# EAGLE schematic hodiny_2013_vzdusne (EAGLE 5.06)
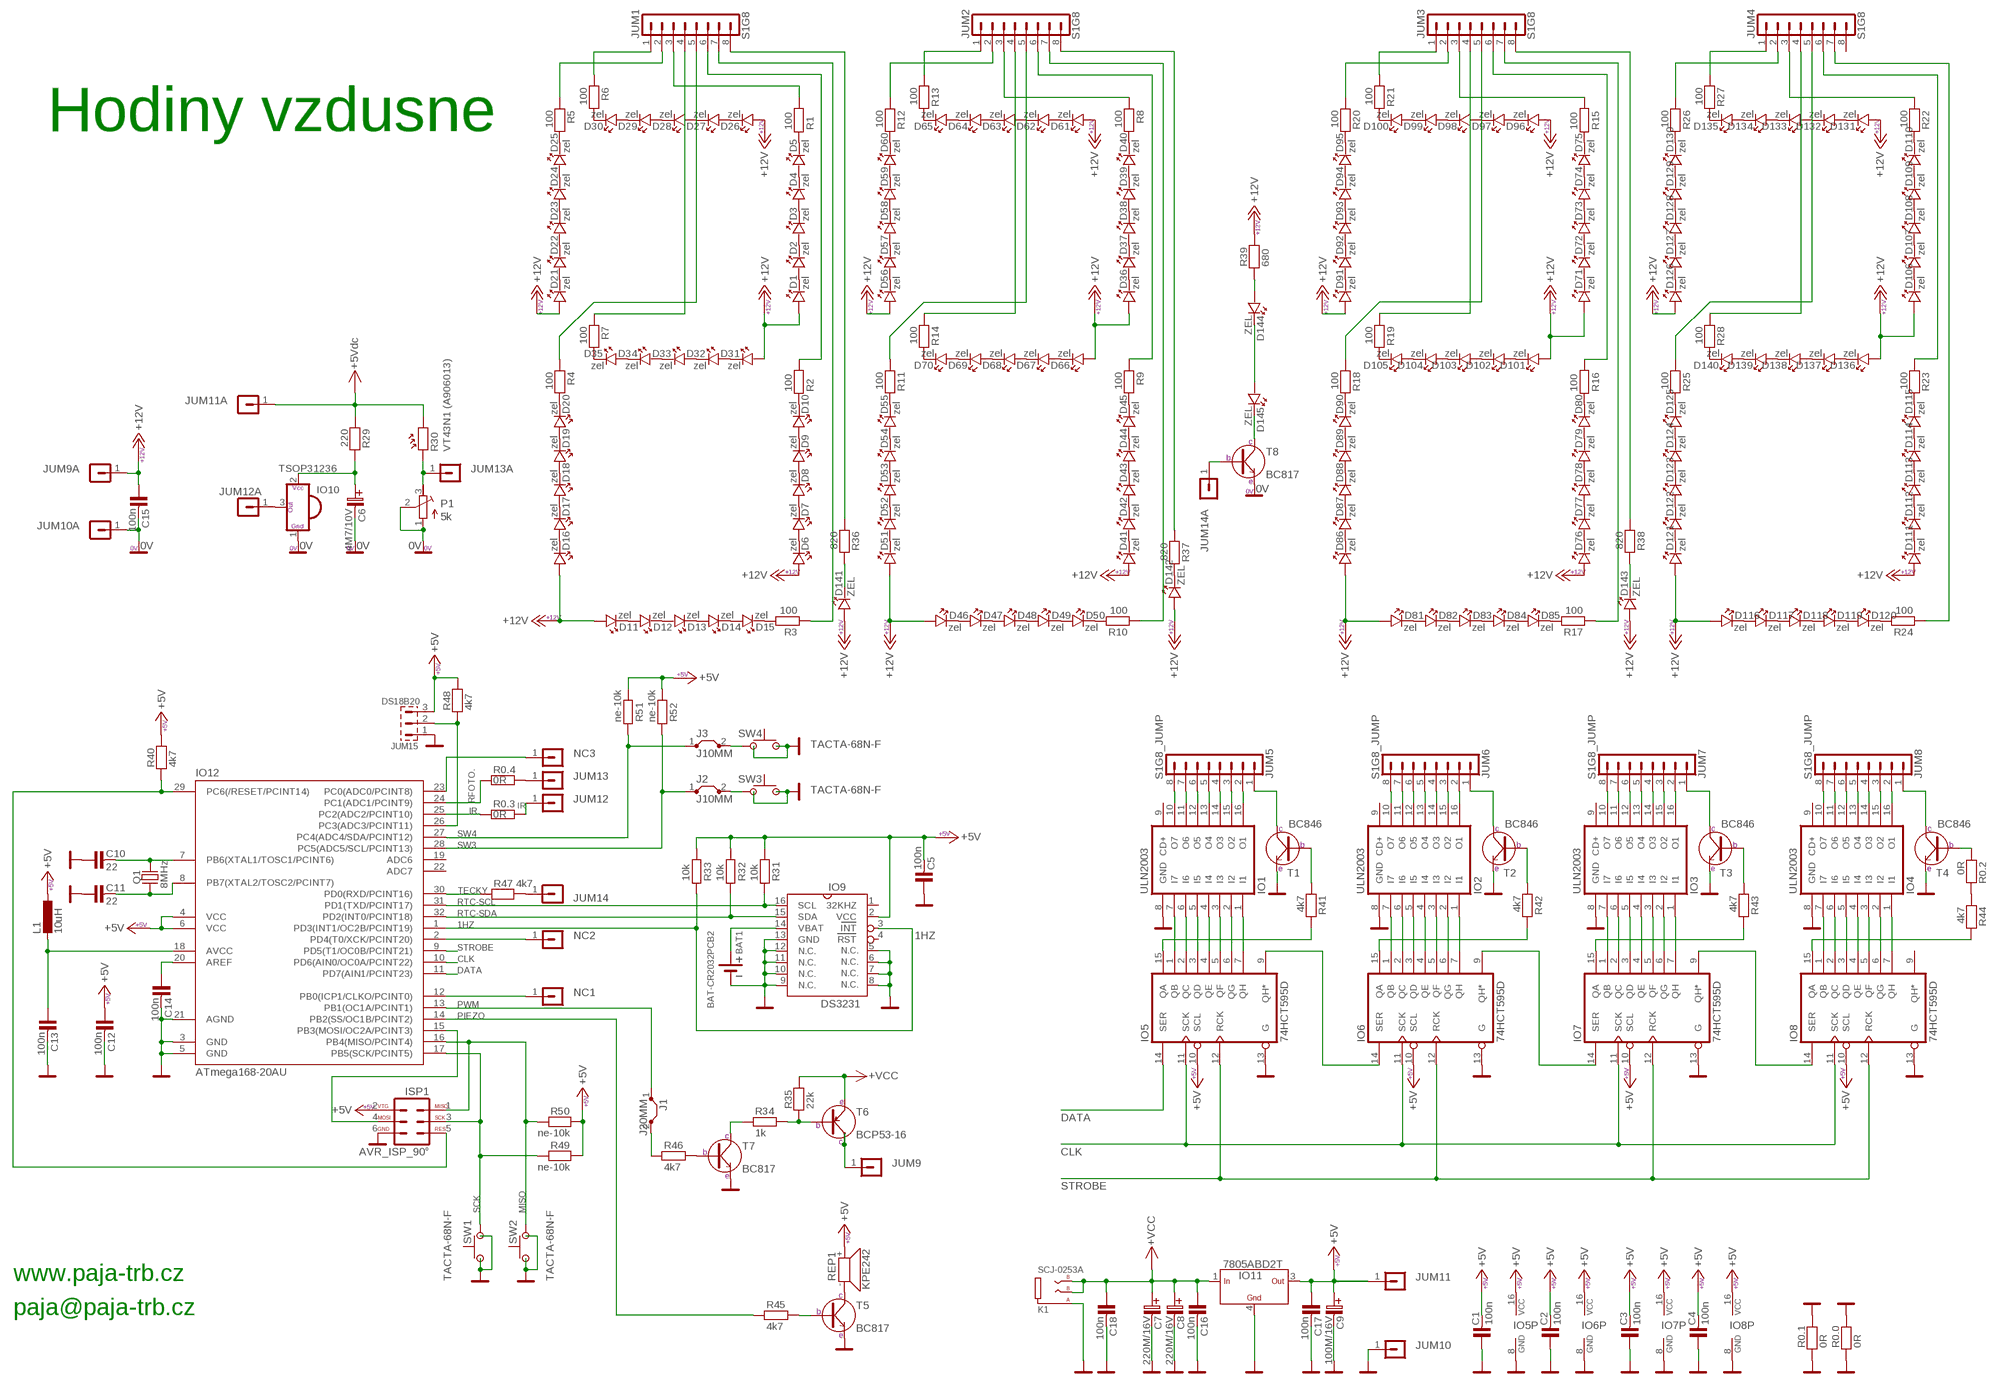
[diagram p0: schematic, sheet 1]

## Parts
BAT1  BAT-CR2032PCB2  2032  [SN2032]
C1  100n  C-KERAMIK_SMD_1206  [1206]
C2  100n  C-KERAMIK_SMD_1206  [1206]
C3  100n  C-KERAMIK_SMD_1206  [1206]
C4  100n  C-KERAMIK_SMD_1206  [1206]
C5  100n  C-KERAMIK_SMD_1206  [1206]
C6  4M7/10V  [A]
C7  220M/16V  #_SMD_POUZDRAF  [C_EL-SMD_F]
C8  220M/16V  #_SMD_POUZDRAF  [C_EL-SMD_F]
C9  100M/16V  100M/16V_SMD  [C_EL-SMD_D]
C10  22  C-KERAMIK_SMD_0805  [0805]
C11  22  C-KERAMIK_SMD_0805  [0805]
C12  100n  C-KERAMIK_SMD_0805  [0805]
C13  100n  C-KERAMIK_SMD_0805  [0805]
C14  100n  C-KERAMIK_SMD_0805  [0805]
C15  100n  C-KERAMIK_SMD_1206  [1206]
C16  100n  C-KERAMIK_SMD_1206  [1206]
C17  100n  C-KERAMIK_SMD_1206  [1206]
C18  100n  C-KERAMIK_SMD_1206  [1206]
D1  zel  LED_5X5  [LED_5X5]
D2  zel  LED_5X5  [LED_5X5]
D3  zel  LED_5X5  [LED_5X5]
D4  zel  LED_5X5  [LED_5X5]
D5  zel  LED_5X5  [LED_5X5]
D6  zel  LED_5X5  [LED_5X5]
D7  zel  LED_5X5  [LED_5X5]
D8  zel  LED_5X5  [LED_5X5]
D9  zel  LED_5X5  [LED_5X5]
D10  zel  LED_5X5  [LED_5X5]
D11  zel  LED_5X5  [LED_5X5]
D12  zel  LED_5X5  [LED_5X5]
D13  zel  LED_5X5  [LED_5X5]
D14  zel  LED_5X5  [LED_5X5]
D15  zel  LED_5X5  [LED_5X5]
D16  zel  LED_5X5  [LED_5X5]
D17  zel  LED_5X5  [LED_5X5]
D18  zel  LED_5X5  [LED_5X5]
D19  zel  LED_5X5  [LED_5X5]
D20  zel  LED_5X5  [LED_5X5]
D21  zel  LED_5X5  [LED_5X5]
D22  zel  LED_5X5  [LED_5X5]
D23  zel  LED_5X5  [LED_5X5]
D24  zel  LED_5X5  [LED_5X5]
D25  zel  LED_5X5  [LED_5X5]
D26  zel  LED_5X5  [LED_5X5]
D27  zel  LED_5X5  [LED_5X5]
D28  zel  LED_5X5  [LED_5X5]
D29  zel  LED_5X5  [LED_5X5]
D30  zel  LED_5X5  [LED_5X5]
D31  zel  LED_5X5  [LED_5X5]
D32  zel  LED_5X5  [LED_5X5]
D33  zel  LED_5X5  [LED_5X5]
D34  zel  LED_5X5  [LED_5X5]
D35  zel  LED_5X5  [LED_5X5]
D36  zel  LED_5X5  [LED_5X5]
D37  zel  LED_5X5  [LED_5X5]
D38  zel  LED_5X5  [LED_5X5]
D39  zel  LED_5X5  [LED_5X5]
D40  zel  LED_5X5  [LED_5X5]
D41  zel  LED_5X5  [LED_5X5]
D42  zel  LED_5X5  [LED_5X5]
D43  zel  LED_5X5  [LED_5X5]
D44  zel  LED_5X5  [LED_5X5]
D45  zel  LED_5X5  [LED_5X5]
D46  zel  LED_5X5  [LED_5X5]
D47  zel  LED_5X5  [LED_5X5]
D48  zel  LED_5X5  [LED_5X5]
D49  zel  LED_5X5  [LED_5X5]
D50  zel  LED_5X5  [LED_5X5]
D51  zel  LED_5X5  [LED_5X5]
D52  zel  LED_5X5  [LED_5X5]
D53  zel  LED_5X5  [LED_5X5]
D54  zel  LED_5X5  [LED_5X5]
D55  zel  LED_5X5  [LED_5X5]
D56  zel  LED_5X5  [LED_5X5]
D57  zel  LED_5X5  [LED_5X5]
D58  zel  LED_5X5  [LED_5X5]
D59  zel  LED_5X5  [LED_5X5]
D60  zel  LED_5X5  [LED_5X5]
D61  zel  LED_5X5  [LED_5X5]
D62  zel  LED_5X5  [LED_5X5]
D63  zel  LED_5X5  [LED_5X5]
D64  zel  LED_5X5  [LED_5X5]
D65  zel  LED_5X5  [LED_5X5]
D66  zel  LED_5X5  [LED_5X5]
D67  zel  LED_5X5  [LED_5X5]
D68  zel  LED_5X5  [LED_5X5]
D69  zel  LED_5X5  [LED_5X5]
D70  zel  LED_5X5  [LED_5X5]
D71  zel  LED_5X5  [LED_5X5]
D72  zel  LED_5X5  [LED_5X5]
D73  zel  LED_5X5  [LED_5X5]
D74  zel  LED_5X5  [LED_5X5]
D75  zel  LED_5X5  [LED_5X5]
D76  zel  LED_5X5  [LED_5X5]
D77  zel  LED_5X5  [LED_5X5]
D78  zel  LED_5X5  [LED_5X5]
D79  zel  LED_5X5  [LED_5X5]
D80  zel  LED_5X5  [LED_5X5]
D81  zel  LED_5X5  [LED_5X5]
D82  zel  LED_5X5  [LED_5X5]
D83  zel  LED_5X5  [LED_5X5]
D84  zel  LED_5X5  [LED_5X5]
D85  zel  LED_5X5  [LED_5X5]
D86  zel  LED_5X5  [LED_5X5]
D87  zel  LED_5X5  [LED_5X5]
D88  zel  LED_5X5  [LED_5X5]
D89  zel  LED_5X5  [LED_5X5]
D90  zel  LED_5X5  [LED_5X5]
D91  zel  LED_5X5  [LED_5X5]
D92  zel  LED_5X5  [LED_5X5]
D93  zel  LED_5X5  [LED_5X5]
D94  zel  LED_5X5  [LED_5X5]
D95  zel  LED_5X5  [LED_5X5]
D96  zel  LED_5X5  [LED_5X5]
D97  zel  LED_5X5  [LED_5X5]
D98  zel  LED_5X5  [LED_5X5]
D99  zel  LED_5X5  [LED_5X5]
D100  zel  LED_5X5  [LED_5X5]
D101  zel  LED_5X5  [LED_5X5]
D102  zel  LED_5X5  [LED_5X5]
D103  zel  LED_5X5  [LED_5X5]
D104  zel  LED_5X5  [LED_5X5]
D105  zel  LED_5X5  [LED_5X5]
D106  zel  LED_5X5  [LED_5X5]
D107  zel  LED_5X5  [LED_5X5]
D108  zel  LED_5X5  [LED_5X5]
D109  zel  LED_5X5  [LED_5X5]
D110  zel  LED_5X5  [LED_5X5]
D111  zel  LED_5X5  [LED_5X5]
D112  zel  LED_5X5  [LED_5X5]
D113  zel  LED_5X5  [LED_5X5]
D114  zel  LED_5X5  [LED_5X5]
D115  zel  LED_5X5  [LED_5X5]
D116  zel  LED_5X5  [LED_5X5]
D117  zel  LED_5X5  [LED_5X5]
D118  zel  LED_5X5  [LED_5X5]
D119  zel  LED_5X5  [LED_5X5]
D120  zel  LED_5X5  [LED_5X5]
D121  zel  LED_5X5  [LED_5X5]
D122  zel  LED_5X5  [LED_5X5]
D123  zel  LED_5X5  [LED_5X5]
D124  zel  LED_5X5  [LED_5X5]
D125  zel  LED_5X5  [LED_5X5]
D126  zel  LED_5X5  [LED_5X5]
D127  zel  LED_5X5  [LED_5X5]
D128  zel  LED_5X5  [LED_5X5]
D129  zel  LED_5X5  [LED_5X5]
D130  zel  LED_5X5  [LED_5X5]
D131  zel  LED_5X5  [LED_5X5]
D132  zel  LED_5X5  [LED_5X5]
D133  zel  LED_5X5  [LED_5X5]
D134  zel  LED_5X5  [LED_5X5]
D135  zel  LED_5X5  [LED_5X5]
D136  zel  LED_5X5  [LED_5X5]
D137  zel  LED_5X5  [LED_5X5]
D138  zel  LED_5X5  [LED_5X5]
D139  zel  LED_5X5  [LED_5X5]
D140  zel  LED_5X5  [LED_5X5]
D141  ZEL  LED_5  [LED_5]
D142  ZEL  LED_5  [LED_5]
D143  ZEL  LED_5  [LED_5]
D144  ZEL  LED_5  [LED_5]
D145  ZEL  LED_5  [LED_5]
IO1  ULN2003  ULN2003AD  [SO16]
IO2  ULN2003  ULN2003AD  [SO16]
IO3  ULN2003  ULN2003AD  [SO16]
IO4  ULN2003  ULN2003AD  [SO16]
IO5  74HCT595D  [SO16]
IO6  74HCT595D  [SO16]
IO7  74HCT595D  [SO16]
IO8  74HCT595D  [SO16]
IO9  DS3231  [SO16L]
IO10  TSOP31236  SFH506  [SFH506]
IO11  7805ABD2T  78D2PAKD2PAK  [D2PAK]
IO12  ATmega168-20AU  MEGA48/88/168-AU  [TQFP32-08]
ISP1  AVR_ISP_90°  [MLW06A]
J1  J20MM  [20]
J2  J10MM  [10]
J3  J10MM  [10]
JUM1  S1G8  S1G8_JUMP  [S1G8_JUM]
JUM2  S1G8  S1G8_JUMP  [S1G8_JUM]
JUM3  S1G8  S1G8_JUMP  [S1G8_JUM]
JUM4  S1G8  S1G8_JUMP  [S1G8_JUM]
JUM5  S1G8_JUMP  [S1G8_JUM]
JUM6  S1G8_JUMP  [S1G8_JUM]
JUM7  S1G8_JUMP  [S1G8_JUM]
JUM8  S1G8_JUMP  [S1G8_JUM]
JUM9  .  S1G1_JUMP  [S1G1_JUM]
JUM9A  .  S1G1_JUMP  [S1G1_JUM]
JUM10  .  S1G1_JUMP  [S1G1_JUM]
JUM10A  .  S1G1_JUMP  [S1G1_JUM]
JUM11  .  S1G1_JUMP  [S1G1_JUM]
JUM11A  .  S1G1_JUMP  [S1G1_JUM]
JUM12  .  S1G1_JUMP  [S1G1_JUM]
JUM12A  .  S1G1_JUMP  [S1G1_JUM]
JUM13  .  S1G1_JUMP  [S1G1_JUM]
JUM13A  .  S1G1_JUMP  [S1G1_JUM]
JUM14  .  S1G1_JUMP  [S1G1_JUM]
JUM14A  .  S1G1_JUMP  [S1G1_JUM]
JUM15  DS18B20  S1G3_JUMP  [S1G3_JUM]
K1  SCJ-0253A  [CON_SCJ-0253A]
L1  10uH  L-EU0204/5  [0204/5]
NC1  S1G1_JUMP  [S1G1_JUM]
NC2  S1G1_JUMP  [S1G1_JUM]
NC3  S1G1_JUMP  [S1G1_JUM]
P1  5k  R-TRIMMTS63Z  [RTRIMTS63Z]
Q1  8MHz  XTAL_HC-49U_SMD  [HC-49US]
R0.0  0R  R_SMD_1206  [1206]
R0.1  0R  R_SMD_1206  [1206]
R0.2  0R  R_SMD_1206  [1206]
R0.3  0R  R_SMD_1206  [1206]
R0.4  0R  R_SMD_1206  [1206]
R1  100  R_SMD_1206  [1206]
R2  100  R_SMD_1206  [1206]
R3  100  R_SMD_1206  [1206]
R4  100  R_SMD_1206  [1206]
R5  100  R_SMD_1206  [1206]
R6  100  R_SMD_1206  [1206]
R7  100  R_SMD_1206  [1206]
R8  100  R_SMD_1206  [1206]
R9  100  R_SMD_1206  [1206]
R10  100  R_SMD_1206  [1206]
R11  100  R_SMD_1206  [1206]
R12  100  R_SMD_1206  [1206]
R13  100  R_SMD_1206  [1206]
R14  100  R_SMD_1206  [1206]
R15  100  R_SMD_1206  [1206]
R16  100  R_SMD_1206  [1206]
R17  100  R_SMD_1206  [1206]
R18  100  R_SMD_1206  [1206]
R19  100  R_SMD_1206  [1206]
R20  100  R_SMD_1206  [1206]
R21  100  R_SMD_1206  [1206]
R22  100  R_SMD_1206  [1206]
R23  100  R_SMD_1206  [1206]
R24  100  R_SMD_1206  [1206]
R25  100  R_SMD_1206  [1206]
R26  100  R_SMD_1206  [1206]
R27  100  R_SMD_1206  [1206]
R28  100  R_SMD_1206  [1206]
R29  220  R_SMD_1206  [1206]
R30  VT43N1 (A906013)  R-FOTO  [R-FOTO]
R31  10k  R_SMD_1206  [1206]
R32  10k  R_SMD_1206  [1206]
R33  10k  R_SMD_1206  [1206]
R34  1k  R_SMD_1206  [1206]
R35  22k  R_SMD_1206  [1206]
R36  820  R_SMD_1206  [1206]
R37  820  R_SMD_1206  [1206]
R38  820  R_SMD_1206  [1206]
R39  680  R_SMD_1206  [1206]
R40  4k7  R_SMD_1206  [1206]
R41  4k7  R_SMD_1206  [1206]
R42  4k7  R_SMD_1206  [1206]
R43  4k7  R_SMD_1206  [1206]
R44  4k7  R_SMD_1206  [1206]
R45  4k7  R_SMD_1206  [1206]
R46  4k7  R_SMD_1206  [1206]
R47  4k7  R_SMD_1206  [1206]
R48  4k7  R_SMD_0805  [0805]
R49  ne-10k  R_SMD_0805  [0805]
R50  ne-10k  R_SMD_0805  [0805]
R51  ne-10k  R_SMD_1206  [1206]
R52  ne-10k  R_SMD_1206  [1206]
REP1  KPE242  [KPE242]
SW1  TACTA-68N-F  P-KSM632B  [P-KSM632B]
SW2  TACTA-68N-F  P-KSM632B  [P-KSM632B]
SW3  TACTA-68N-F  P-KSM632B  [P-KSM632B]
SW4  TACTA-68N-F  P-KSM632B  [P-KSM632B]
T1  BC846  [SOT-23]
T2  BC846  [SOT-23]
T3  BC846  [SOT-23]
T4  BC846  [SOT-23]
T5  BC817  [SOT-23]
T6  BCP53-16  BCP53  [SOT223]
T7  BC817  [SOT-23]
T8  BC817  [SOT-23]

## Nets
0V: C6.-(C_EL-) C15.2 IO10.1(GND) JUM10A.1 P1.1(E) P1.2(S) T8.2(E)
1HZ: IO9.3(INT) IO12.1(PD3(INT1/OC2B/PCINT19)) R33.1
+5V: C1.2 C2.2 C3.2 C4.2 C5.2 C9.+(C_EL+) C12.1 C17.1 IO5.10(SCL) IO5.16(VCC) IO6.10(SCL) IO6.16(VCC) IO7.10(SCL) IO7.16(VCC) IO8.10(SCL) IO8.16(VCC) IO9.2(VCC) IO11.3(OUT) IO12.4(VCC) IO12.6(VCC) ISP1.2 JUM11.1 JUM15.3 L1.1 R31.2 R32.2 R33.2 R40.2 R48.2 R49.1 R50.1 R51.2 R52.2 REP1.+
+5VDC: JUM11A.1 R29.1 R30.2 ; supply symbol labelled +5Vdc
+12V: C15.1 D1.A D6.A D11.A D16.A D21.A D26.A D31.A D36.A D41.A D46.A D51.A D56.A D61.A D66.A D71.A D76.A D81.A D86.A D91.A D96.A D101.A D106.A D111.A D116.A D121.A D126.A D131.A D136.A D141.A D142.A D143.A JUM9A.1 R39.2
CLK: IO5.11(SCK) IO6.11(SCK) IO7.11(SCK) IO8.11(SCK) IO12.10(PD6(AIN0/OC0A/PCINT22))
DATA: IO5.14(SER) IO12.11(PD7(AIN1/PCINT23))
DATA1: IO5.9(QH*) IO6.14(SER)
DATA2: IO6.9(QH*) IO7.14(SER)
DATA3: IO7.9(QH*) IO8.14(SER)
DS18B20: IO12.26(PC3(ADC3/PCINT11)) JUM15.2 R48.1
GND: BAT1.- C1.1 C2.1 C3.1 C4.1 C5.1 C7.-(C_EL-) C8.-(C_EL-) C9.-(C_EL-) C10.1 C11.1 C12.2 C13.2 C14.2 C16.2 C17.2 C18.2 IO1.8(GND) IO2.8(GND) IO3.8(GND) IO4.8(GND) IO5.8(GND) IO5.13(G) IO6.8(GND) IO6.13(G) IO7.8(GND) IO7.13(G) IO8.8(GND) IO8.13(G) IO9.5 IO9.6 IO9.7 IO9.8 IO9.9 IO9.10 IO9.11 IO9.12 IO9.13(GND) IO11.4(GND) IO12.3(GND) IO12.5(GND) IO12.21(AGND) ISP1.6 JUM10.1 JUM15.1 K1.1(A) R0.0.1 R0.0.2 R0.1.1 R0.1.2 SW1.1 SW1.A SW1.B SW2.1 SW2.A SW2.B SW3.1 SW3.A SW3.B SW4.1 SW4.A SW4.B T1.2(E) T2.2(E) T3.2(E) T4.2(E) T5.2(E) T7.2(E)
IR: JUM12.1 R0.3.2
IR.: IO12.25(PC2(ADC2/PCINT10)) R0.3.1
IR_1: IO10.3(OUT) JUM12A.1
MISO: IO12.16(PB4(MISO/PCINT4)) ISP1.1 R50.2 SW2.2
MOSI: IO12.15(PB3(MOSI/OC2A/PCINT3)) ISP1.4
N$1: D1.K D2.A
N$2: D2.K D3.A
N$3: D3.K D4.A
N$4: D4.K D5.A
N$5: D6.K D7.A
N$6: D7.K D8.A
N$7: D8.K D9.A
N$8: D9.K D10.A
N$9: D11.K D12.A
N$10: D12.K D13.A
N$11: D13.K D14.A
N$12: D14.K D15.A
N$13: D16.K D17.A
N$14: D17.K D18.A
N$15: D18.K D19.A
N$16: D19.K D20.A
N$17: D21.K D22.A
N$18: D22.K D23.A
N$19: D23.K D24.A
N$20: D24.K D25.A
N$21: D26.K D27.A
N$22: D27.K D28.A
N$23: D28.K D29.A
N$24: D29.K D30.A
N$25: D31.K D32.A
N$26: D32.K D33.A
N$27: D33.K D34.A
N$28: D34.K D35.A
N$29: D36.K D37.A
N$30: D37.K D38.A
N$31: D38.K D39.A
N$32: D39.K D40.A
N$33: D41.K D42.A
N$34: D42.K D43.A
N$35: D43.K D44.A
N$36: D44.K D45.A
N$37: D46.K D47.A
N$38: D47.K D48.A
N$39: D48.K D49.A
N$40: D49.K D50.A
N$41: D51.K D52.A
N$42: D52.K D53.A
N$43: D53.K D54.A
N$44: D54.K D55.A
N$45: D56.K D57.A
N$46: D57.K D58.A
N$47: D58.K D59.A
N$48: D59.K D60.A
N$49: D61.K D62.A
N$50: D62.K D63.A
N$51: D63.K D64.A
N$52: D64.K D65.A
N$53: D66.K D67.A
N$54: D67.K D68.A
N$55: D68.K D69.A
N$56: D69.K D70.A
N$57: D5.K R1.1
N$58: D10.K R2.1
N$59: D15.K R3.2
N$60: D20.K R4.2
N$61: D35.K R7.2
N$62: D25.K R5.2
N$63: D30.K R6.2
N$64: D40.K R8.2
N$65: D45.K R9.2
N$66: D50.K R10.2
N$67: D55.K R11.2
N$68: D60.K R12.2
N$69: D65.K R13.2
N$70: D70.K R14.2
N$71: D141.K R36.2
N$72: D142.K R37.2
N$73: D71.K D72.A
N$74: D72.K D73.A
N$75: D73.K D74.A
N$76: D74.K D75.A
N$77: D76.K D77.A
N$78: D77.K D78.A
N$79: D78.K D79.A
N$80: D79.K D80.A
N$81: D81.K D82.A
N$82: D82.K D83.A
N$83: D83.K D84.A
N$84: D84.K D85.A
N$85: D86.K D87.A
N$86: D87.K D88.A
N$87: D88.K D89.A
N$88: D89.K D90.A
N$89: D91.K D92.A
N$90: D92.K D93.A
N$91: D93.K D94.A
N$92: D94.K D95.A
N$93: D96.K D97.A
N$94: D97.K D98.A
N$95: D98.K D99.A
N$96: D99.K D100.A
N$97: D101.K D102.A
N$98: D102.K D103.A
N$99: D103.K D104.A
N$100: D104.K D105.A
N$101: D106.K D107.A
N$102: D107.K D108.A
N$103: D108.K D109.A
N$104: D109.K D110.A
N$105: D111.K D112.A
N$106: D112.K D113.A
N$107: D113.K D114.A
N$108: D114.K D115.A
N$109: D116.K D117.A
N$110: D117.K D118.A
N$111: D118.K D119.A
N$112: D119.K D120.A
N$113: D121.K D122.A
N$114: D122.K D123.A
N$115: D123.K D124.A
N$116: D124.K D125.A
N$117: D126.K D127.A
N$118: D127.K D128.A
N$119: D128.K D129.A
N$120: D129.K D130.A
N$121: D131.K D132.A
N$122: D132.K D133.A
N$123: D133.K D134.A
N$124: D134.K D135.A
N$125: D136.K D137.A
N$126: D137.K D138.A
N$127: D138.K D139.A
N$128: D139.K D140.A
N$129: D75.K R15.1
N$130: D80.K R16.1
N$131: D85.K R17.2
N$132: D90.K R18.2
N$133: D105.K R19.2
N$134: D95.K R20.2
N$135: D100.K R21.2
N$136: D110.K R22.2
N$137: D115.K R23.2
N$138: D120.K R24.2
N$139: D125.K R25.2
N$140: D130.K R26.2
N$141: D135.K R27.2
N$142: D140.K R28.2
N$143: D143.K R38.2
N$144: IO1.16(O1) JUM5.2
N$145: D144.A R39.1
N$146: D144.K D145.A
N$147: IO1.1(I1) IO5.7(QH)
N$148: IO1.2(I2) IO5.6(QG)
N$149: IO1.3(I3) IO5.5(QF)
N$150: IO1.4(I4) IO5.4(QE)
N$151: IO1.5(I5) IO5.3(QD)
N$152: IO1.6(I6) IO5.2(QC)
N$153: IO1.7(I7) IO5.1(QB)
N$154: JUM1.1 R6.1
N$155: JUM1.2 R5.1
N$156: JUM1.3 R1.2
N$157: JUM1.4 R7.1
N$158: JUM1.5 R4.1
N$159: JUM1.6 R2.2
N$160: JUM1.7 R3.1
N$161: JUM1.8 R36.1
N$162: JUM2.1 R13.1
N$163: JUM2.2 R12.1
N$164: JUM2.3 R8.1
N$165: JUM2.4 R14.1
N$166: JUM2.5 R11.1
N$167: JUM2.6 R9.1
N$168: JUM2.7 R10.1
N$169: JUM2.8 R37.1
N$170: JUM3.1 R21.1
N$171: JUM3.2 R20.1
N$172: JUM3.3 R15.2
N$173: JUM3.4 R19.1
N$174: JUM3.5 R18.1
N$175: JUM3.6 R16.2
N$176: JUM3.7 R17.1
N$177: JUM3.8 R38.1
N$178: JUM4.1 R27.1
N$179: JUM4.2 R26.1
N$180: JUM4.3 R22.1
N$181: JUM4.4 R28.1
N$182: JUM4.5 R25.1
N$183: JUM4.6 R23.1
N$184: JUM4.7 R24.1
N$185: IO1.15(O2) JUM5.3
N$186: IO1.14(O3) JUM5.4
N$187: IO1.13(O4) JUM5.5
N$188: IO1.12(O5) JUM5.6
N$189: IO1.11(O6) JUM5.7
N$190: IO1.10(O7) JUM5.8
N$191: R41.1 T1.1(B)
N$192: JUM5.1 T1.3(C)
N$193: IO5.15(QA) R41.2
N$194: IO2.1(I1) IO6.7(QH)
N$195: IO2.2(I2) IO6.6(QG)
N$196: IO2.3(I3) IO6.5(QF)
N$197: IO2.4(I4) IO6.4(QE)
N$198: IO2.5(I5) IO6.3(QD)
N$199: IO2.6(I6) IO6.2(QC)
N$200: IO2.7(I7) IO6.1(QB)
N$201: IO2.16(O1) JUM6.2
N$202: IO2.15(O2) JUM6.3
N$203: IO2.14(O3) JUM6.4
N$204: IO2.13(O4) JUM6.5
N$205: IO2.12(O5) JUM6.6
N$206: IO2.11(O6) JUM6.7
N$207: IO2.10(O7) JUM6.8
N$208: R42.1 T2.1(B)
N$209: JUM6.1 T2.3(C)
N$210: IO6.15(QA) R42.2
N$211: C6.+(C_EL+) IO10.2(VCC) R29.2
N$212: IO3.1(I1) IO7.7(QH)
N$213: IO3.2(I2) IO7.6(QG)
N$214: IO3.3(I3) IO7.5(QF)
N$215: IO3.4(I4) IO7.4(QE)
N$216: IO3.5(I5) IO7.3(QD)
N$217: IO3.6(I6) IO7.2(QC)
N$218: IO3.7(I7) IO7.1(QB)
N$219: IO3.16(O1) JUM7.2
N$220: IO3.15(O2) JUM7.3
N$221: IO3.14(O3) JUM7.4
N$222: IO3.13(O4) JUM7.5
N$223: IO3.12(O5) JUM7.6
N$224: IO3.11(O6) JUM7.7
N$225: IO3.10(O7) JUM7.8
N$226: R43.1 T3.1(B)
N$227: JUM7.1 T3.3(C)
N$228: IO7.15(QA) R43.2
N$229: IO4.1(I1) IO8.7(QH)
N$230: IO4.2(I2) IO8.6(QG)
N$231: IO4.3(I3) IO8.5(QF)
N$232: IO4.4(I4) IO8.4(QE)
N$233: IO4.5(I5) IO8.3(QD)
N$234: IO4.6(I6) IO8.2(QC)
N$235: IO4.7(I7) IO8.1(QB)
N$236: IO4.16(O1) JUM8.2
N$237: IO4.15(O2) JUM8.3
N$238: IO4.14(O3) JUM8.4
N$239: IO4.13(O4) JUM8.5
N$240: IO4.12(O5) JUM8.6
N$241: IO4.11(O6) JUM8.7
N$242: IO4.10(O7) JUM8.8
N$243: R0.2.2 R44.1
N$244: JUM8.1 T4.3(C)
N$245: IO8.15(QA) R44.2
N$246: JUM14A.1 T8.1(B)
N$248: JUM14.1 R47.1
N$249: R0.2.1 T4.1(B)
N$250: JUM13A.1 P1.3(A) R30.1
N$251: BAT1.+ IO9.14(VBAT)
N$252: REP1.- T5.3(C)
N$253: R45.2 T5.1(B)
N$254: JUM9.1 T6.2(C) T6.4(C)
N$255: R34.2 R35.1 T6.1(B)
N$256: C13.1 IO12.18(AVCC) L1.2
N$257: C11.2 IO12.8(PB7(XTAL2/TOSC2/PCINT7)) Q1.1
N$258: C10.2 IO12.7(PB6(XTAL1/TOSC1/PCINT6)) Q1.2
N$259: JUM13.1 R0.4.2
N$261: R46.2 T7.1(B)
N$262: C14.1 IO12.20(AREF)
N$263: IO12.2(PD4(T0/XCK/PCINT20)) NC2.1
N$265: IO12.12(PB0(ICP1/CLKO/PCINT0)) NC1.1
N$266: IO12.23(PC0(ADC0/PCINT8)) NC3.1
N$268: J1.2 R46.1
N$269: J2.2 SW3.2
N$270: J3.2 SW4.2
N$271: R34.1 T7.3(C)
N$272: D145.K T8.3(C)
PIEZO: IO12.14(PB2(SS/OC1B/PCINT2)) R45.1
PWM: IO12.13(PB1(OC1A/PCINT1)) J1.1
RESET: IO12.29(PC6(/RESET/PCINT14)) ISP1.5 R40.1
RFOTO.: IO12.24(PC1(ADC1/PCINT9)) R0.4.1
RTC-SCL: IO9.16(SCL) IO12.31(PD1(TXD/PCINT17)) R31.1
RTC-SDA: IO9.15(SDA) IO12.32(PD2(INT0/PCINT18)) R32.1
SCK: IO12.17(PB5(SCK/PCINT5)) ISP1.3 R49.2 SW1.2
STROBE: IO5.12(RCK) IO6.12(RCK) IO7.12(RCK) IO8.12(RCK) IO12.9(PD5(T1/OC0B/PCINT21))
SW3: IO12.28(PC5(ADC5/SCL/PCINT13)) J2.1 R52.1
SW4: IO12.27(PC4(ADC4/SDA/PCINT12)) J3.1 R51.1
TECKY: IO12.30(PD0(RXD/PCINT16)) R47.2
VCC: C7.+(C_EL+) C8.+(C_EL+) C16.1 C18.1 IO11.1(IN) K1.2(B1) K1.3(B2) R35.2 T6.3(E) ; supply symbol labelled +VCC
Unconnected: IO1.9(CD+) IO2.9(CD+) IO3.9(CD+) IO4.9(CD+) IO8.9(QH*) IO9.1(32KHZ) IO9.4(RST) IO12.19(ADC6) IO12.22(ADC7) JUM4.8

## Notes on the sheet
- Hodiny vzdusne
- www.paja-trb.cz
- paja@paja-trb.cz

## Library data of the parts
BAT1 = #PaJa_31:2032: Battery 2032
C1-C5 C10-C18 = #PaJa_31:C-KERAMIK: Kondenzator - keramicky
C6 = #PaJa_C-tantal_SMD:4M7/10V
C7 C8 = #PaJa_C-el_2:#_SMD_POUZDRA
C9 = #PaJa_C-el_2:100M/16V
D1-D145 = #PaJa_31:LED: LED - jednobarevna
IO1-IO4 = uln-udn:ULN2003A: DRIVER ARRAY
IO5-IO8 = 74xx-eu:74*595: 8-bit SHIFT REGISTER, output latch
IO9 = #PaJa_31:DS3231: RTC
IO10 = #PaJa_31:SFH506: Optoprijimac s tvarovacem - 36 kHz nebo 56 kHz ekv. TSOP31236
IO11 = #PaJa_31:78??: Stabilizátor - 1A a 1,5A ?? - napeti => 05, 06, 08, 09, 12, 15, 18, 20, 24 => 1,5A ?? - napeti => 10, 12, 15, 18 => 1A S ?? - napeti => 05, 09, 10, 12, 15, 18, 24 => 2A T ?? - napeti => 05 => 3A
IO12 = avr-7:MEGA48/88/168
ISP1 = #PaJa_31:AVR_ISP: AVR ISP konektor (dle standardu)
J1-J3 = jumper:J: Bridge
JUM1-JUM8 = #PaJa_konektory:S1G8_JUMP: Radove konektory - koliky - 8x
JUM9 JUM9A JUM10 JUM10A JUM11 JUM11A JUM12 JUM12A JUM13 JUM13A JUM14 JUM14A NC1-NC3 = #PaJa_konektory:S1G1_JUMP: Radove konektory - koliky - 1x
JUM15 = #PaJa_konektory:S1G3_JUMP: Radove konektory - koliky - 3x
K1 = #PaJa_konektory:SCJ-0253A: 2,5mm JACK - mono TME
L1 = resistor:L-EU: INDUCTOR, European symbol
P1 = rcl:R-TRIMM: Trimm resistor
Q1 = #PaJa_31:XTAL_HC-49U: Krystal - 1MHz - 48MHz
R0.0 R0.1-R0.4 R1-R29 R31-R52 = #PaJa_31:R: Rezistor
R30 = #PaJa_31:R-FOTO: Foto odpor
REP1 = #PaJa_31:KPE242: Piezo-sirenka - 70dB - 3V az 16V
SW1-SW4 = #PaJa_prepinace:P-KSM632B: &micro;-tlacitko
T1-T4 = #PaJa_31:BC846: SMD tranzistor - NPN - ekv. BC546
T5 T7 T8 = #PaJa_31:BC817: SMD tranzistor - NPN - ekv. BC337
T6 = #PaJa_31:BCP53: PNP, Uce 80V, Ic 1A, P 1,3W Pouzdro SOT223, Kmitocet 115MHz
